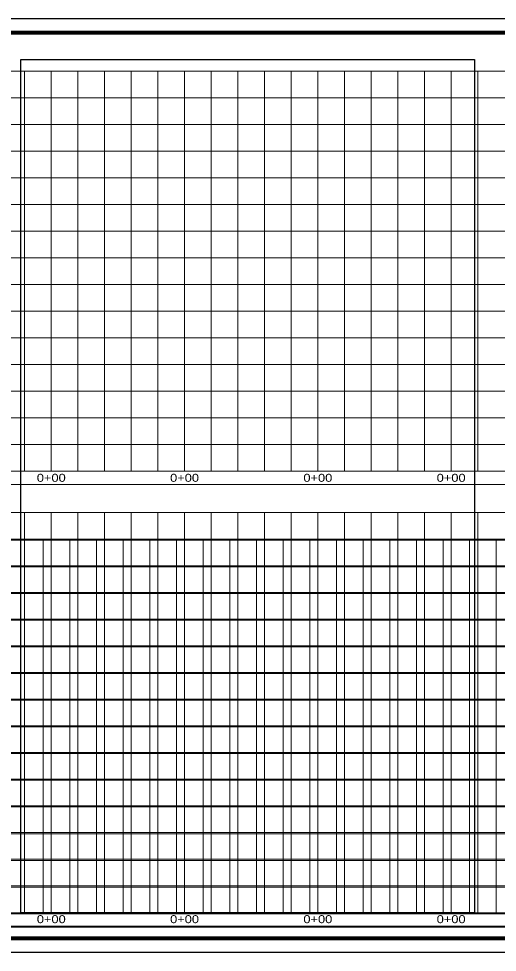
# Model space of a CAD drawing. Extents: x 2246932 to 2264252, y 7095151 to 7098651.
# Drawn here: x 2250469 to 2252265, y 7095151 to 7098651 of the extents above; entities that cross this region are included whole.
import ezdxf
from ezdxf.enums import TextEntityAlignment as Align

# ---------------------------------------------------------------- set-up
doc = ezdxf.new("R2010")
doc.units = 0
doc.header["$LTSCALE"] = 12
for name, color, linetype, lineweight in [('1', 7, 'Continuous', 80), ('59', 7, 'Continuous', 13), ('62', 7, 'Continuous', 13), ('63', 7, 'Continuous', 25)]:
    doc.layers.add(name, color=color, linetype=linetype, lineweight=lineweight)
doc.layers.add('22', color=7, linetype='Continuous')

msp = doc.modelspace()

# ---------------------------------------------------------------- linework, layer by layer
at = {"layer": '1'}
for p, q in [((2264052.09, 7098598.35), (2247157.09, 7098598.35)), ((2247157.09, 7095203.35), (2264052.09, 7095203.35))]:
    msp.add_line(p, q, dxfattribs=at)
at = {"layer": '1', "lineweight": 25}
msp.add_line((2247104.59, 7095150.85), (2264104.59, 7095150.85), dxfattribs=at)
msp.add_lwpolyline([(2264104.59, 7095150.85), (2264104.59, 7098650.85), (2247104.59, 7098650.85), (2247104.59, 7095150.85)], dxfattribs=at)
at = {"layer": '59'}
for p, q in [((2247310.97, 7096695.64), (2262610.97, 7096695.64)), ((2250560.97, 7095295.64), (2250560.97, 7096695.64)), ((2250660.97, 7095295.64), (2250660.97, 7096695.64)), ((2250760.97, 7095295.64), (2250760.97, 7096695.64)), ((2250860.97, 7095295.64), (2250860.97, 7096695.64)), ((2250960.97, 7096695.64), (2250960.97, 7095295.64)), ((2251060.97, 7095295.64), (2251060.97, 7096695.64)), ((2251160.97, 7095295.64), (2251160.97, 7096695.64)), ((2251260.97, 7095295.64), (2251260.97, 7096695.64)), ((2251360.97, 7095295.64), (2251360.97, 7096695.64)), ((2251460.97, 7096695.64), (2251460.97, 7095295.64)), ((2251560.97, 7095295.64), (2251560.97, 7096695.64)), ((2251660.97, 7095295.64), (2251660.97, 7096695.64)), ((2251760.97, 7095295.64), (2251760.97, 7096695.64)), ((2251860.97, 7095295.64), (2251860.97, 7096695.64)), ((2251960.97, 7096695.64), (2251960.97, 7095295.64)), ((2252060.97, 7095295.64), (2252060.97, 7096695.64)), ((2252160.97, 7095295.64), (2252160.97, 7096695.64)), ((2252260.97, 7095295.64), (2252260.97, 7096695.64)), ((2262610.97, 7095295.64), (2247310.97, 7095295.64)), ((2262610.97, 7095245.64), (2247310.97, 7095245.64))]:
    msp.add_line(p, q, dxfattribs=at)
for points in [[(2247460.97, 7096595.64), (2262460.97, 7096595.64), (2262610.97, 7096595.64)], [(2247460.97, 7096495.64), (2262460.97, 7096495.64), (2262610.97, 7096495.64)], [(2247460.97, 7096395.64), (2262460.97, 7096395.64), (2262610.97, 7096395.64)], [(2247460.97, 7096295.64), (2262460.97, 7096295.64), (2262610.97, 7096295.64)], [(2247460.97, 7096195.64), (2262460.97, 7096195.64), (2262610.97, 7096195.64)], [(2247454.92, 7096095.64), (2262460.97, 7096095.64), (2262610.97, 7096095.64)], [(2247460.97, 7095995.64), (2262460.97, 7095995.64), (2262610.97, 7095995.64)], [(2247460.97, 7095895.64), (2262460.97, 7095895.64), (2262610.97, 7095895.64)], [(2247460.97, 7095795.64), (2262460.97, 7095795.64), (2262610.97, 7095795.64)], [(2247460.97, 7095695.64), (2262460.97, 7095695.64), (2262610.97, 7095695.64)], [(2247460.97, 7095595.64), (2262460.97, 7095595.64), (2262610.97, 7095595.64)], [(2247460.97, 7095495.64), (2262460.97, 7095495.64), (2262610.97, 7095495.64)], [(2247460.97, 7095395.64), (2262460.97, 7095395.64), (2262610.97, 7095395.64)]]:
    msp.add_lwpolyline(points, dxfattribs=at)
at = {"layer": '62'}
for p, q in [((2247941.45, 7098454.14), (2263241.45, 7098454.14)), ((2250491.45, 7098454.14), (2250491.45, 7096954.14)), ((2250591.45, 7098454.14), (2250591.45, 7096954.14)), ((2250691.45, 7098454.14), (2250691.45, 7096954.14)), ((2250791.45, 7098454.14), (2250791.45, 7096954.14)), ((2250891.45, 7098454.14), (2250891.45, 7096954.14)), ((2250991.45, 7098454.14), (2250991.45, 7096954.14)), ((2251091.45, 7098454.14), (2251091.45, 7096954.14)), ((2251191.45, 7098454.14), (2251191.45, 7096954.14)), ((2251291.45, 7098454.14), (2251291.45, 7096954.14)), ((2251391.45, 7098454.14), (2251391.45, 7096954.14)), ((2251491.45, 7098454.14), (2251491.45, 7096954.14)), ((2251591.45, 7098454.14), (2251591.45, 7096954.14)), ((2251691.45, 7098454.14), (2251691.45, 7096954.14)), ((2251791.45, 7098454.14), (2251791.45, 7096954.14)), ((2251891.45, 7098454.14), (2251891.45, 7096954.14)), ((2251991.45, 7098454.14), (2251991.45, 7096954.14)), ((2252091.45, 7098454.14), (2252091.45, 7096954.14)), ((2252191.45, 7098454.14), (2252191.45, 7096954.14)), ((2259241.45, 7097654.14), (2249441.45, 7097654.14)), ((2263241.45, 7096954.14), (2247941.45, 7096954.14)), ((2263241.45, 7096904.14), (2247941.45, 7096904.14)), ((2247941.45, 7096799.51), (2263241.45, 7096799.51)), ((2250491.45, 7096799.51), (2250491.45, 7095299.51)), ((2250591.45, 7096799.51), (2250591.45, 7095299.51)), ((2250691.45, 7096799.51), (2250691.45, 7095299.51)), ((2250791.45, 7096799.51), (2250791.45, 7095299.51)), ((2250891.45, 7096799.51), (2250891.45, 7095299.51)), ((2250991.45, 7096799.51), (2250991.45, 7095299.51)), ((2251091.45, 7096799.51), (2251091.45, 7095299.51)), ((2251191.45, 7096799.51), (2251191.45, 7095299.51)), ((2251291.45, 7096799.51), (2251291.45, 7095299.51)), ((2251391.45, 7096799.51), (2251391.45, 7095299.51)), ((2251491.45, 7096799.51), (2251491.45, 7095299.51)), ((2251591.45, 7096799.51), (2251591.45, 7095299.51)), ((2251691.45, 7096799.51), (2251691.45, 7095299.51)), ((2251791.45, 7096799.51), (2251791.45, 7095299.51)), ((2251891.45, 7096799.51), (2251891.45, 7095299.51)), ((2251991.45, 7096799.51), (2251991.45, 7095299.51)), ((2252091.45, 7096799.51), (2252091.45, 7095299.51)), ((2252191.45, 7096799.51), (2252191.45, 7095299.51)), ((2259241.45, 7095999.51), (2249441.45, 7095999.51)), ((2263241.45, 7095299.51), (2247941.45, 7095299.51)), ((2263241.45, 7095249.51), (2247941.45, 7095249.51))]:
    msp.add_line(p, q, dxfattribs=at)
for points in [[(2248091.45, 7098354.14), (2263091.45, 7098354.14), (2263241.45, 7098354.14)], [(2248091.45, 7098254.14), (2263091.45, 7098254.14), (2263241.45, 7098254.14)], [(2248091.45, 7098154.14), (2263091.45, 7098154.14), (2263241.45, 7098154.14)], [(2248091.45, 7098054.14), (2263091.45, 7098054.14), (2263241.45, 7098054.14)], [(2248091.45, 7097954.14), (2263091.45, 7097954.14), (2263241.45, 7097954.14)], [(2248091.45, 7097854.14), (2263091.45, 7097854.14), (2263241.45, 7097854.14)], [(2248091.45, 7097754.14), (2263091.45, 7097754.14), (2263241.45, 7097754.14)], [(2248091.45, 7097654.14), (2263091.45, 7097654.14), (2263241.45, 7097654.14)], [(2248091.45, 7097554.14), (2263091.45, 7097554.14), (2263241.45, 7097554.14)], [(2248091.45, 7097454.14), (2263091.45, 7097454.14), (2263241.45, 7097454.14)], [(2248091.45, 7097354.14), (2263091.45, 7097354.14), (2263241.45, 7097354.14)], [(2248091.45, 7097254.14), (2263091.45, 7097254.14), (2263241.45, 7097254.14)], [(2248091.45, 7097154.14), (2263091.45, 7097154.14), (2263241.45, 7097154.14)], [(2248091.45, 7097054.14), (2263091.45, 7097054.14), (2263241.45, 7097054.14)], [(2248091.45, 7096699.51), (2263091.45, 7096699.51), (2263241.45, 7096699.51)], [(2248091.45, 7096599.51), (2263091.45, 7096599.51), (2263241.45, 7096599.51)], [(2248091.45, 7096499.51), (2263091.45, 7096499.51), (2263241.45, 7096499.51)], [(2248091.45, 7096399.51), (2263091.45, 7096399.51), (2263241.45, 7096399.51)], [(2248091.45, 7096299.51), (2263091.45, 7096299.51), (2263241.45, 7096299.51)], [(2248091.45, 7096199.51), (2263091.45, 7096199.51), (2263241.45, 7096199.51)], [(2248091.45, 7096099.51), (2263091.45, 7096099.51), (2263241.45, 7096099.51)], [(2248091.45, 7095999.51), (2263091.45, 7095999.51), (2263241.45, 7095999.51)], [(2248091.45, 7095899.51), (2263091.45, 7095899.51), (2263241.45, 7095899.51)], [(2248091.45, 7095799.51), (2263091.45, 7095799.51), (2263241.45, 7095799.51)], [(2248091.45, 7095699.51), (2263091.45, 7095699.51), (2263241.45, 7095699.51)], [(2248091.45, 7095599.51), (2263091.45, 7095599.51), (2263241.45, 7095599.51)], [(2248091.45, 7095499.51), (2263091.45, 7095499.51), (2263241.45, 7095499.51)], [(2248091.45, 7095399.51), (2263091.45, 7095399.51), (2263241.45, 7095399.51)]]:
    msp.add_lwpolyline(points, dxfattribs=at)
at = {"layer": '63'}
msp.add_lwpolyline([(2252179.49, 7095298.54), (2250477.33, 7095298.54), (2250477.33, 7098498.04), (2252179.49, 7098498.04)], close=True, dxfattribs=at)

# ---------------------------------------------------------------- texts
at = {"layer": '22', "width": 1.2}
for p in [(2250591.45, 7096914.74), (2251091.45, 7096914.74), (2251591.45, 7096914.74), (2252091.45, 7096914.74), (2250591.45, 7095260.11), (2251091.45, 7095260.11), (2251591.45, 7095260.11), (2252091.45, 7095260.11)]:
    msp.add_text('0+00', height=30, dxfattribs=at).set_placement(p, align=Align.CENTER)

doc.saveas('drawing.dxf')
